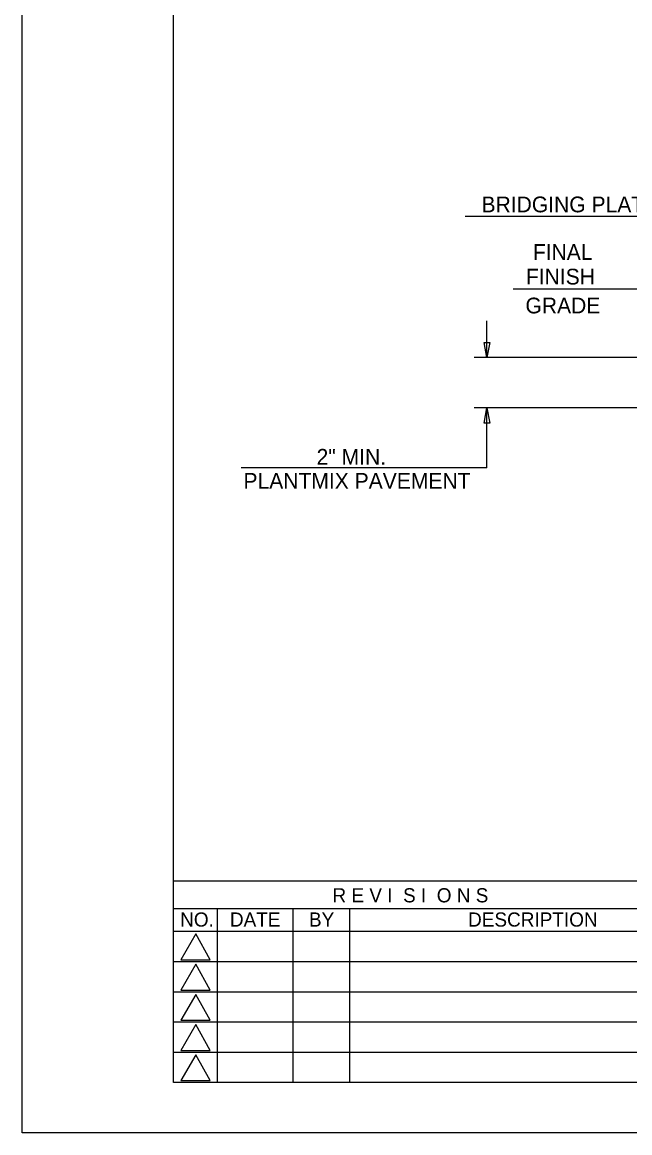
# Model space of a CAD drawing. Extents: x 0 to 11.3, y 0 to 7.8.
# Drawn here: x 0 to 2.009, y 0 to 3.675 of the extents above; entities that cross this region are included whole.
import ezdxf

# ---------------------------------------------------------------- set-up
doc = ezdxf.new("R2010")
doc.units = 0
for name, color, linetype in [('BORDER_ANNO_Cutsheet', 7, 'Continuous'), ('BRDG_ANNO_Anno-Sheet', 7, 'Continuous'), ('BRDG_ANNO_General-Notes', 7, 'Continuous'), ('BRDG_BASE_Active-Point', 7, 'Continuous')]:
    doc.layers.add(name, color=color, linetype=linetype)

msp = doc.modelspace()

# ---------------------------------------------------------------- linework, layer by layer
at = {"layer": 'BORDER_ANNO_Cutsheet'}
msp.add_lwpolyline([(0, 7.3333), (11.3333, 7.3333), (11.3333, 0), (0, 0)], close=True, dxfattribs=at)
at = {"layer": 'BRDG_ANNO_Anno-Sheet'}
for p, q in [((0.5, 0.8333), (6.4167, 0.8333)), ((0.5, 0.7417), (2.3333, 0.7417)), ((0.6458, 0.1667), (0.6458, 0.7417)), ((0.8958, 0.1667), (0.8958, 0.7417)), ((1.0833, 0.1667), (1.0833, 0.7398)), ((0.4992, 0.6667), (2.3333, 0.6667)), ((0.4992, 0.5667), (2.3333, 0.5667)), ((0.4992, 0.4667), (2.3333, 0.4667)), ((0.4992, 0.3667), (2.3333, 0.3667)), ((0.4992, 0.2667), (2.3333, 0.2667))]:
    msp.add_line(p, q, dxfattribs=at)
msp.add_lwpolyline([(0.5, 7.1667), (11.1667, 7.1667), (11.1667, 0.1667), (0.5, 0.1667)], close=True, dxfattribs=at)
for points in [[(0.5742, 0.6581), (0.5248, 0.5725), (0.6215, 0.5725), (0.5742, 0.6581)], [(0.5742, 0.5581), (0.5248, 0.4725), (0.6215, 0.4725), (0.5742, 0.5581)], [(0.5742, 0.4581), (0.5248, 0.3725), (0.6215, 0.3725), (0.5742, 0.4581)], [(0.5742, 0.3581), (0.5248, 0.2725), (0.6215, 0.2725), (0.5742, 0.3581)], [(0.5742, 0.2581), (0.5248, 0.1725), (0.6215, 0.1725), (0.5742, 0.2581)]]:
    msp.add_lwpolyline(points, dxfattribs=at)
at = {"layer": 'BRDG_ANNO_General-Notes'}
for p, q in [((2.788, 3.0317), (1.4643, 3.0317)), ((2.1133, 2.7918), (1.623, 2.7918)), ((1.5367, 2.5654), (1.5367, 2.6864)), ((1.5273, 2.6154), (1.546, 2.6154)), ((1.5367, 2.5654), (1.5273, 2.6154)), ((1.546, 2.6154), (1.5367, 2.5654)), ((2.0841, 2.5654), (1.4941, 2.5654)), ((2.0867, 2.3987), (1.4941, 2.3987)), ((1.5273, 2.3487), (1.5367, 2.3987)), ((1.5367, 2.2003), (1.5367, 2.3987)), ((1.5367, 2.3987), (1.546, 2.3487)), ((1.546, 2.3487), (1.5273, 2.3487)), ((1.5367, 2.2003), (0.7238, 2.2003))]:
    msp.add_line(p, q, dxfattribs=at)
at = {"layer": 'BRDG_BASE_Active-Point'}
msp.add_line((0, 0), (0, 0), dxfattribs=at)

# ---------------------------------------------------------------- texts
at = {"layer": 'BRDG_ANNO_Anno-Sheet'}
for s, height, p in [('R E V I  S I  O N S', 0.046875, (1.0258, 0.7625)), ('NO.', 0.04688, (0.5222, 0.6823)), ('DATE', 0.04688, (0.6867, 0.6823)), ('BY', 0.04688, (0.9481, 0.6823)), ('DESCRIPTION', 0.046875, (1.4742, 0.6823))]:
    msp.add_text(s, height=height, dxfattribs=at).set_placement(p)
at = {"layer": 'BRDG_ANNO_General-Notes'}
for s, height, p in [('BRIDGING PLATE', 0.052083, (1.5186, 3.046)), ('FINAL', 0.05208, (1.6883, 2.8885)), ('FINISH', 0.05208, (1.6654, 2.8071)), ('GRADE', 0.05208, (1.6639, 2.7115)), ('2" MIN.', 0.05208, (0.9733, 2.2109)), ('PLANTMIX PAVEMENT', 0.052083, (0.7315, 2.1313))]:
    msp.add_text(s, height=height, dxfattribs=at).set_placement(p)

doc.saveas('drawing.dxf')
